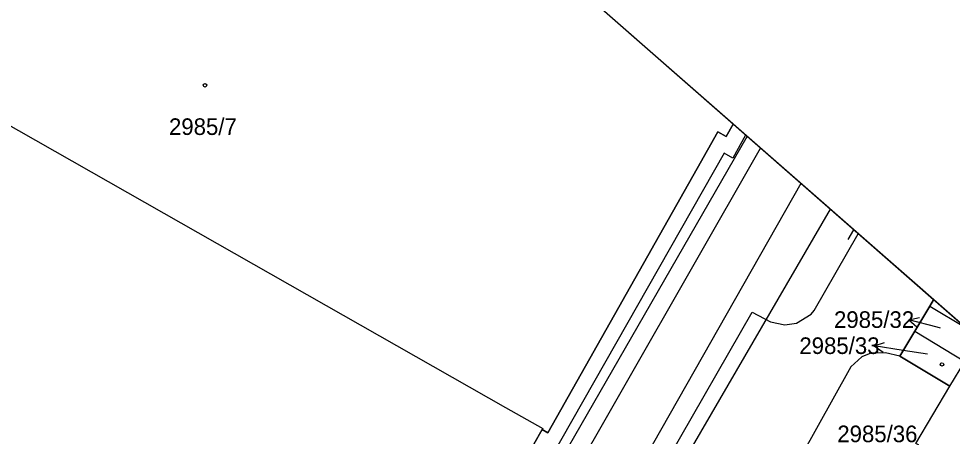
# Model space of a CAD drawing. Extents: x -620475 to -619963, y -1123010 to -1122510.
# Drawn here: x -620108.2 to -620012.5, y -1122755.5 to -1122712.8 of the extents above; entities that cross this region are included whole.
import ezdxf

# ---------------------------------------------------------------- set-up
doc = ezdxf.new("R2010")
doc.units = 0
for name, color, linetype in [('Hranice parcel', 7, 'Continuous'), ('Parcelní čísla', 7, 'Continuous'), ('Pop  PČ popisy', 7, 'Continuous'), ('Rámečky', 7, 'Continuous'), ('Rámečky-tisk', 7, 'Continuous'), ('VAS stoka', 7, 'Continuous'), ('VAS vodovod', 7, 'Continuous'), ('Vnitřní kresba', 7, 'Continuous'), ('Věcná břemena k části', 7, 'Continuous'), ('Značky budov', 7, 'Continuous')]:
    doc.layers.add(name, color=color, linetype=linetype)

msp = doc.modelspace()

# ---------------------------------------------------------------- linework, layer by layer
at = {"layer": 'Hranice parcel'}
for p, q in [((-620014.432, -1122741.565), (-620014.82, -1122742.21)), ((-620014.82, -1122742.21), (-620016.36, -1122744.78)), ((-620014.82, -1122742.21), (-620011.179, -1122744.41)), ((-620016.36, -1122744.78), (-620011.23, -1122747.87)), ((-620012.77, -1122750.41), (-620011.23, -1122747.87))]:
    msp.add_line(p, q, dxfattribs=at)
for points in [[(-620129.52, -1122710.96), (-620124.48, -1122713.98), (-620124.94, -1122714.79), (-620058.31, -1122752.59), (-620054.51, -1122754.74), (-620054.56, -1122754.84)], [(-620054.56, -1122754.84), (-620053.98, -1122755.17), (-620038.67, -1122728.11), (-620036.56, -1122724.38), (-620035.71, -1122724.86), (-620034.98, -1122723.59)], [(-620016.36, -1122744.78), (-620017.89, -1122747.34), (-620012.77, -1122750.41)], [(-620015.21, -1122767.58), (-620013.28, -1122764.14), (-620010.56, -1122759.32), (-620016.25, -1122756.27), (-620012.77, -1122750.41)], [(-620122.58, -1122783.75), (-620090.7, -1122801.75), (-620090.59, -1122801.55), (-620087.3, -1122795.66), (-620086.96, -1122795.04), (-620090.3, -1122793.12), (-620089.73, -1122792.12), (-620086.43, -1122793.99), (-620082.68, -1122796.11), (-620083.01, -1122796.68), (-620082.45, -1122797), (-620082.12, -1122796.42), (-620078.46, -1122798.5), (-620077.82, -1122797.38), (-620073.87, -1122790.42), (-620073.02, -1122790.9), (-620071.46, -1122788.15), (-620072.31, -1122787.67), (-620056.64, -1122759.92), (-620057.24, -1122759.58), (-620055.41, -1122756.34), (-620054.56, -1122754.84)]]:
    msp.add_lwpolyline(points, dxfattribs=at)
at = {"layer": 'Pop  PČ popisy'}
for p, q in [((-620016.979, -1122743.603), (-620015.882, -1122743.379)), ((-620014.08, -1122744.38), (-620016.979, -1122743.603)), ((-620016.979, -1122743.603), (-620016.141, -1122744.346)), ((-620013.72, -1122744.48), (-620014.08, -1122744.38)), ((-620020.524, -1122746.271), (-620019.457, -1122745.933)), ((-620017.56, -1122746.74), (-620020.524, -1122746.271)), ((-620020.524, -1122746.271), (-620019.613, -1122746.922)), ((-620015.05, -1122747.14), (-620017.56, -1122746.74))]:
    msp.add_line(p, q, dxfattribs=at)
at = {"layer": 'Rámečky'}
msp.add_line((-619962.948, -1122786.6), (-620279.069, -1122510.073), dxfattribs=at)
at = {"layer": 'Rámečky-tisk'}
msp.add_lwpolyline([(-620158.492, -1123010.143), (-619962.948, -1122786.6), (-620279.069, -1122510.073)], dxfattribs=at)
at = {"layer": 'VAS stoka'}
for p, q in [((-620052.94, -1122758.439), (-620033.543, -1122724.847)), ((-620023.18, -1122735.39), (-620022.612, -1122734.409))]:
    msp.add_line(p, q, dxfattribs=at)
msp.add_lwpolyline([(-620055.26, -1122766.37), (-620053.564, -1122763.408), (-620052.846, -1122762.154), (-620032.173, -1122726.045)], dxfattribs=at)
at = {"layer": 'VAS vodovod'}
for points in [[(-620028.042, -1122729.66), (-620082.75, -1122825.82)], [(-620025.037, -1122732.288), (-620059.31, -1122791.147), (-620066.473, -1122802.261), (-620067.023, -1122803.23), (-620067.856, -1122804.615), (-620080.94, -1122827.26)]]:
    msp.add_lwpolyline(points, dxfattribs=at)
at = {"layer": 'Vnitřní kresba'}
for p, q in [((-620033.713, -1122724.698), (-620035.03, -1122727.06)), ((-620035.9, -1122726.57), (-620054.1, -1122758.47)), ((-620035.03, -1122727.06), (-620035.9, -1122726.57)), ((-620026.67, -1122742.66), (-620022.166, -1122734.799)), ((-620026.97, -1122743.05), (-620026.67, -1122742.66)), ((-620041.55, -1122757.64), (-620033.04, -1122742.83)), ((-620033.04, -1122742.83), (-620031.15, -1122743.81)), ((-620028.49, -1122743.97), (-620026.97, -1122743.05)), ((-620031.15, -1122743.81), (-620029.7, -1122744.11)), ((-620029.7, -1122744.11), (-620028.49, -1122743.97)), ((-620021.79, -1122747.41), (-620022.92, -1122748.42)), ((-620020.88, -1122747.04), (-620021.79, -1122747.41)), ((-620019.38, -1122747), (-620020.88, -1122747.04)), ((-620017.89, -1122747.34), (-620019.38, -1122747)), ((-620022.92, -1122748.42), (-620031.91, -1122764.55))]:
    msp.add_line(p, q, dxfattribs=at)
at = {"layer": 'Věcná břemena k části'}
msp.add_line((-620014.432, -1122741.565), (-620034.98, -1122723.59), dxfattribs=at)
msp.add_line((-620014.432, -1122741.565), (-620034.98, -1122723.59), dxfattribs=at)
msp.add_line((-620014.432, -1122741.565), (-620034.98, -1122723.59), dxfattribs=at)
msp.add_line((-620014.432, -1122741.565), (-620034.98, -1122723.59), dxfattribs=at)
for points in [[(-620034.98, -1122723.59), (-620035.71, -1122724.86), (-620036.56, -1122724.38), (-620038.67, -1122728.11), (-620053.98, -1122755.17), (-620054.56, -1122754.84), (-620055.41, -1122756.34)], [(-620034.98, -1122723.59), (-620035.71, -1122724.86), (-620036.56, -1122724.38), (-620038.67, -1122728.11), (-620053.98, -1122755.17), (-620054.56, -1122754.84), (-620055.41, -1122756.34)], [(-620034.98, -1122723.59), (-620035.71, -1122724.86), (-620036.56, -1122724.38), (-620038.67, -1122728.11), (-620053.98, -1122755.17), (-620054.56, -1122754.84), (-620055.41, -1122756.34)], [(-620034.98, -1122723.59), (-620035.71, -1122724.86), (-620036.56, -1122724.38), (-620038.67, -1122728.11), (-620053.98, -1122755.17), (-620054.56, -1122754.84), (-620055.41, -1122756.34)], [(-620016.25, -1122756.27), (-620012.77, -1122750.41), (-620017.89, -1122747.34), (-620016.36, -1122744.78), (-620014.82, -1122742.21), (-620014.432, -1122741.565)], [(-620016.25, -1122756.27), (-620012.77, -1122750.41), (-620017.89, -1122747.34), (-620016.36, -1122744.78), (-620014.82, -1122742.21), (-620014.432, -1122741.565)], [(-620016.25, -1122756.27), (-620012.77, -1122750.41), (-620017.89, -1122747.34), (-620016.36, -1122744.78), (-620014.82, -1122742.21), (-620014.432, -1122741.565)], [(-620016.25, -1122756.27), (-620012.77, -1122750.41), (-620017.89, -1122747.34), (-620016.36, -1122744.78), (-620014.82, -1122742.21), (-620014.432, -1122741.565)]]:
    msp.add_lwpolyline(points, dxfattribs=at)
at = {"layer": 'Značky budov'}
for centre in [(-620089.127, -1122719.609), (-620013.577, -1122748.179)]:
    msp.add_circle(centre, 0.175, dxfattribs=at)

# ---------------------------------------------------------------- texts
at = {"layer": 'Parcelní čísla'}
for s, p in [('2985/7', (-620092.82, -1122724.69)), ('2985/32', (-620024.646, -1122744.44)), ('2985/33', (-620028.196, -1122747.11)), ('2985/36', (-620024.308, -1122756.14))]:
    msp.add_text(s, height=1.7, dxfattribs=at).set_placement(p)

doc.saveas('drawing.dxf')
